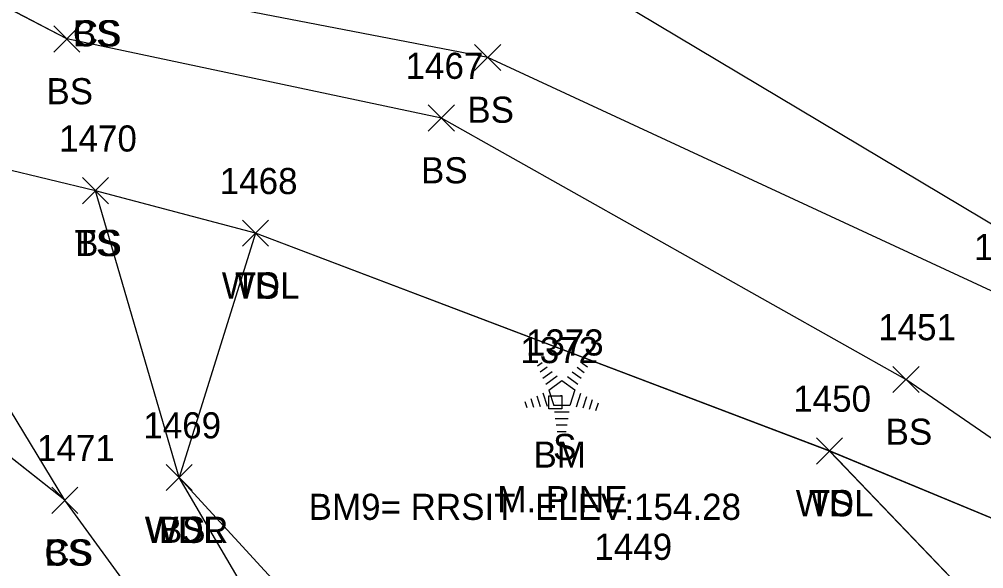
# Model space of a CAD drawing. Extents: x 1415642 to 1422021, y 544543 to 547232.
# Drawn here: x 1416207 to 1416280.8, y 546804.9 to 546847 of the extents above; entities that cross this region are included whole.
import ezdxf

# ---------------------------------------------------------------- set-up
doc = ezdxf.new("R2010")
doc.units = 0
for name, color, linetype in [('C_A', 7, 'Continuous'), ('C_C', 7, 'Continuous'), ('C_I', 7, 'Continuous'), ('CPBM', 7, 'Continuous'), ('L_A', 7, 'Continuous'), ('L_C', 7, 'Continuous'), ('L_I', 7, 'Continuous'), ('L_TIC', 7, 'Continuous'), ('LAWA', 7, 'Continuous'), ('LELB', 7, 'Continuous'), ('LTC', 7, 'Continuous')]:
    doc.layers.add(name, color=color, linetype=linetype)

msp = doc.modelspace()

# ---------------------------------------------------------------- linework, layer by layer
at = {"layer": 'CPBM'}
for p, q in [((1416247.487, 546817.14), (1416247.487, 546818.14)), ((1416247.487, 546818.14), (1416248.487, 546818.14)), ((1416248.487, 546818.14), (1416248.487, 546817.14)), ((1416248.487, 546817.14), (1416247.487, 546817.14)), ((1416247.99, 546817.641), (1416247.99, 546817.641)), ((1416247.99, 546817.641), (1416247.99, 546817.641))]:
    msp.add_line(p, q, dxfattribs=at)
at = {"layer": 'L_TIC'}
for points in [[(1416209.605, 546844.462), (1416211.605, 546846.462)], [(1416211.605, 546844.462), (1416209.605, 546846.462)], [(1416241.805, 546843.045), (1416243.805, 546845.045)], [(1416243.805, 546843.045), (1416241.805, 546845.045)], [(1416238.261, 546838.408), (1416240.261, 546840.408)], [(1416240.261, 546838.408), (1416238.261, 546840.408)], [(1416211.797, 546832.843), (1416213.797, 546834.843)], [(1416213.797, 546832.843), (1416211.797, 546834.843)], [(1416211.797, 546832.843), (1416213.797, 546834.843)], [(1416213.797, 546832.843), (1416211.797, 546834.843)], [(1416224.048, 546829.585), (1416226.048, 546831.585)], [(1416226.048, 546829.585), (1416224.048, 546831.585)], [(1416224.048, 546829.585), (1416226.048, 546831.585)], [(1416226.048, 546829.585), (1416224.048, 546831.585)], [(1416273.803, 546818.392), (1416275.803, 546820.392)], [(1416275.803, 546818.392), (1416273.803, 546820.392)], [(1416267.957, 546812.918), (1416269.957, 546814.918)], [(1416269.957, 546812.918), (1416267.957, 546814.918)], [(1416267.957, 546812.918), (1416269.957, 546814.918)], [(1416269.957, 546812.918), (1416267.957, 546814.918)], [(1416267.957, 546812.918), (1416269.957, 546814.918)], [(1416269.957, 546812.918), (1416267.957, 546814.918)], [(1416218.207, 546810.881), (1416220.207, 546812.881)], [(1416220.207, 546810.881), (1416218.207, 546812.881)], [(1416218.207, 546810.881), (1416220.207, 546812.881)], [(1416220.207, 546810.881), (1416218.207, 546812.881)], [(1416218.207, 546810.881), (1416220.207, 546812.881)], [(1416220.207, 546810.881), (1416218.207, 546812.881)], [(1416209.45, 546809.142), (1416211.45, 546811.142)], [(1416211.45, 546809.142), (1416209.45, 546811.142)], [(1416209.45, 546809.142), (1416211.45, 546811.142)], [(1416211.45, 546809.142), (1416209.45, 546811.142)]]:
    msp.add_lwpolyline(points, dxfattribs=at)
at = {"layer": 'LAWA'}
for points in [[(1416268.957, 546813.918), (1416225.048, 546830.585), (1416219.207, 546811.881)], [(1416268.958, 546813.914), (1416225.049, 546830.584), (1416219.21, 546811.878)], [(1416347.347, 546811.628), (1416313.073, 546810.868), (1416310.342, 546806.721), (1416303.679, 546799.518), (1416268.957, 546813.918)], [(1416347.344, 546811.625), (1416313.072, 546810.867), (1416310.343, 546806.722), (1416303.677, 546799.515), (1416268.958, 546813.914)], [(1416278.113, 546774.248), (1416236.511, 546793), (1416219.207, 546811.881)], [(1416278.115, 546774.25), (1416236.513, 546792.999), (1416219.21, 546811.878)]]:
    msp.add_lwpolyline(points, dxfattribs=at)
at = {"layer": 'LELB'}
for points in [[(1416210.449, 546810.143), (1416187.238, 546828.497), (1416172.356, 546839.03), (1416162.908, 546845.636), (1416145.696, 546861.763), (1416125.163, 546875.536), (1416093.403, 546901.435), (1416075.184, 546919.901), (1416045.659, 546942.323), (1416039.773, 546946.289), (1416015.879, 546971.975), (1415979.907, 546993.699), (1415946.506, 547018.197), (1415914.221, 547042.269), (1415877.244, 547066.677), (1415845.5, 547087.741)], [(1416210.45, 546810.142), (1416187.236, 546828.498), (1416172.351, 546839.033), (1416162.906, 546845.637), (1416145.693, 546861.764), (1416125.164, 546875.535), (1416093.403, 546901.434), (1416075.185, 546919.898), (1416045.659, 546942.323), (1416039.768, 546946.292), (1416015.881, 546971.972), (1415979.908, 546993.697), (1415946.504, 547018.199), (1415914.218, 547042.271), (1415877.246, 547066.675), (1415845.502, 547087.738)], [(1416396.185, 546650.28), (1416389.93, 546664.102), (1416375.33, 546699.79), (1416360.485, 546732.701), (1416344.12, 546775.761), (1416313.073, 546810.868), (1416283.754, 546829.86), (1416246.424, 546852.162), (1416221.38, 546861.319), (1416210.744, 546868.876), (1416211.398, 546870.405), (1416221.96, 546889.067)], [(1416396.186, 546650.28), (1416389.931, 546664.101), (1416375.333, 546699.787), (1416360.487, 546732.701), (1416344.123, 546775.762), (1416313.072, 546810.867), (1416283.754, 546829.861), (1416246.425, 546852.163), (1416221.377, 546861.32), (1416210.749, 546868.874), (1416211.4, 546870.404), (1416221.965, 546889.067)], [(1416225.048, 546830.585), (1416212.797, 546833.843), (1416194.801, 546838.18), (1416194.662, 546841.719), (1416184.984, 546843.165), (1416179.483, 546844.903), (1416167.887, 546851.572), (1416170.548, 546858.498), (1416166.265, 546865.71), (1416168.887, 546872.01), (1416167.385, 546871.708), (1416162.57, 546875.357), (1416165.046, 546879.987), (1416171.514, 546876.268)], [(1416225.049, 546830.584), (1416212.797, 546833.845), (1416194.799, 546838.183), (1416194.662, 546841.718), (1416184.984, 546843.165), (1416179.486, 546844.901), (1416167.885, 546851.573), (1416170.55, 546858.497), (1416166.265, 546865.71), (1416168.891, 546872.009), (1416167.387, 546871.708), (1416162.572, 546875.356), (1416165.05, 546879.986), (1416171.516, 546876.267)], [(1416399.906, 546654.534), (1416394.347, 546666.375), (1416375.333, 546699.787), (1416357.077, 546731.493), (1416339.454, 546773.581), (1416310.343, 546806.722), (1416282.706, 546825.534), (1416242.807, 546844.041), (1416212.625, 546849.893), (1416203.831, 546852.661), (1416197.941, 546856.205), (1416209.641, 546861.986)], [(1416399.907, 546654.532), (1416394.345, 546666.378), (1416375.33, 546699.79), (1416357.074, 546731.494), (1416339.456, 546773.581), (1416310.342, 546806.721), (1416282.704, 546825.53), (1416242.805, 546844.045), (1416212.627, 546849.893), (1416203.833, 546852.66), (1416197.943, 546856.205), (1416209.643, 546861.986)], [(1416487.567, 546505.93), (1416480.706, 546505.117), (1416469.863, 546502.717), (1416462.762, 546510.547), (1416442.834, 546541.19), (1416430.44, 546560.715), (1416424.351, 546585.185), (1416398.34, 546624.279), (1416389.664, 546643.264), (1416377.296, 546653.034), (1416344.541, 546704.054), (1416343.421, 546724.766), (1416329.349, 546768.045), (1416303.679, 546799.518), (1416274.803, 546819.392), (1416239.261, 546839.408), (1416210.605, 546845.462), (1416203.474, 546849.211), (1416195, 546854.494)], [(1416487.569, 546505.931), (1416480.706, 546505.118), (1416469.858, 546502.715), (1416462.759, 546510.548), (1416442.834, 546541.191), (1416430.438, 546560.718), (1416424.353, 546585.182), (1416398.34, 546624.281), (1416389.663, 546643.265), (1416377.298, 546653.032), (1416344.543, 546704.052), (1416343.424, 546724.765), (1416329.347, 546768.045), (1416303.677, 546799.515), (1416274.804, 546819.396), (1416239.262, 546839.409), (1416210.611, 546845.46), (1416203.478, 546849.209), (1416195.004, 546854.493)], [(1416307.151, 546711.363), (1416298.601, 546718.219), (1416262.672, 546753.939), (1416226.79, 546787.66), (1416210.45, 546810.142), (1416201.524, 546824.858), (1416194.801, 546838.18), (1416185.88, 546835.278), (1416179.92, 546838.455), (1416184.984, 546843.165), (1416189.856, 546849.7)], [(1416307.151, 546711.363), (1416298.6, 546718.221), (1416262.673, 546753.94), (1416226.789, 546787.661), (1416210.449, 546810.143), (1416201.526, 546824.856), (1416194.799, 546838.183), (1416185.88, 546835.279), (1416179.923, 546838.454), (1416184.984, 546843.165), (1416189.857, 546849.7)], [(1416313.42, 546715.929), (1416294.819, 546728.93), (1416263.752, 546753.418), (1416231.452, 546790.983), (1416219.21, 546811.878), (1416212.797, 546833.845)], [(1416313.417, 546715.931), (1416294.816, 546728.934), (1416263.754, 546753.423), (1416231.45, 546790.984), (1416219.207, 546811.881), (1416212.797, 546833.843)], [(1416331.534, 546697.519), (1416334.081, 546729.58), (1416320.995, 546761.855), (1416292.621, 546789.208), (1416268.957, 546813.918)], [(1416331.537, 546697.516), (1416334.08, 546729.581), (1416320.995, 546761.856), (1416292.623, 546789.21), (1416268.958, 546813.914)]]:
    msp.add_lwpolyline(points, dxfattribs=at)
at = {"layer": 'LTC'}
for p, q in [((1416246.615, 546820.434), (1416246.97, 546820.692)), ((1416250.014, 546820.675), (1416250.433, 546820.37)), ((1416246.825, 546819.969), (1416247.354, 546820.353)), ((1416247.035, 546819.503), (1416247.738, 546820.014)), ((1416249.272, 546819.978), (1416249.951, 546819.484)), ((1416249.643, 546820.326), (1416250.192, 546819.927)), ((1416247.244, 546819.037), (1416248.123, 546819.675)), ((1416247.469, 546818.582), (1416248.48, 546819.317)), ((1416248.48, 546819.317), (1416249.478, 546818.592)), ((1416248.9, 546819.63), (1416249.71, 546819.041)), ((1416247.469, 546818.582), (1416247.856, 546817.389)), ((1416249.478, 546818.592), (1416249.086, 546817.389)), ((1416245.648, 546817.714), (1416245.8, 546817.246)), ((1416246.103, 546817.93), (1416246.315, 546817.279)), ((1416246.559, 546818.147), (1416246.83, 546817.311)), ((1416247.014, 546818.363), (1416247.345, 546817.344)), ((1416249.915, 546818.321), (1416249.577, 546817.281)), ((1416250.36, 546818.071), (1416250.072, 546817.186)), ((1416250.804, 546817.821), (1416250.567, 546817.091)), ((1416249.086, 546817.389), (1416247.856, 546817.389)), ((1416251.248, 546817.57), (1416251.062, 546816.996)), ((1416249.048, 546816.889), (1416247.903, 546816.889)), ((1416248.964, 546816.389), (1416247.976, 546816.389)), ((1416248.88, 546815.889), (1416248.049, 546815.889)), ((1416248.797, 546815.389), (1416248.122, 546815.389))]:
    msp.add_line(p, q, dxfattribs=at)

# ---------------------------------------------------------------- texts
at = {"layer": 'C_A'}
msp.add_text('BM', height=2, dxfattribs=at).set_placement((1416246.305, 546812.641))
at = {"layer": 'C_C'}
msp.add_text('BM9= RRSIT  ELEV:154.28', height=2, dxfattribs=at).set_placement((1416229.108, 546808.641))
at = {"layer": 'C_I'}
msp.add_text('1372', height=2, dxfattribs=at).set_placement((1416245.297, 546820.641))
at = {"layer": 'L_A'}
for s, p in [('CS', (1416211.068, 546844.893)), ('BS', (1416211.068, 546844.893)), ('BS', (1416209.046, 546840.462)), ('BS', (1416241.246, 546839.045)), ('BS', (1416237.702, 546834.408)), ('TS', (1416211.207, 546828.843)), ('BS', (1416211.238, 546828.843)), ('WDL', (1416222.465, 546825.585)), ('TS', (1416223.457, 546825.585)), ('BS', (1416273.244, 546814.392)), ('S', (1416247.806, 546813.226)), ('WDL', (1416266.375, 546808.918)), ('WDL', (1416266.375, 546808.918)), ('TS', (1416267.367, 546808.918)), ('WDR', (1416216.569, 546806.881)), ('WDL', (1416216.624, 546806.881)), ('BS', (1416217.648, 546806.881)), ('CS', (1416208.891, 546805.142)), ('BS', (1416208.891, 546805.142))]:
    msp.add_text(s, height=2, dxfattribs=at).set_placement(p)
at = {"layer": 'L_C'}
msp.add_text('M. PINE', height=2, dxfattribs=at).set_placement((1416243.538, 546809.226))
at = {"layer": 'L_I'}
for s, p in [('1467', (1416236.521, 546842.408)), ('1470', (1416210.018, 546836.843)), ('1470', (1416210.018, 546836.843)), ('1468', (1416222.307, 546833.585)), ('1468', (1416222.307, 546833.585)), ('1452', (1416280.012, 546828.53)), ('1451', (1416272.677, 546822.392)), ('1373', (1416245.727, 546821.226)), ('1450', (1416266.178, 546816.918)), ('1450', (1416266.178, 546816.918)), ('1450', (1416266.178, 546816.918)), ('1469', (1416216.459, 546814.881)), ('1469', (1416216.459, 546814.881)), ('1469', (1416216.459, 546814.881)), ('1471', (1416208.324, 546813.142)), ('1471', (1416208.324, 546813.142)), ('1449', (1416250.967, 546805.581))]:
    msp.add_text(s, height=2, dxfattribs=at).set_placement(p)
at = {"layer": 'LTC'}
msp.add_text('.', height=1.037, rotation=270, dxfattribs=at).set_placement((1416248.363, 546818.33))

doc.saveas('drawing.dxf')
